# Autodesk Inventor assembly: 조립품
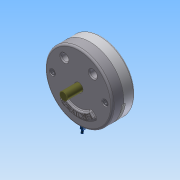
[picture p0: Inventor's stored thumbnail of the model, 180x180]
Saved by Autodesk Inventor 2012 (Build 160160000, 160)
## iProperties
Created: 2015-04
Part Number: 조립품
Document SubType Name: Assembly
Designer: net
Author: net
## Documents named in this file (10)
- C:\Users\net\Desktop\450405V1014\조립품.iam
- C:\Users\net\Desktop\450405V1014\본체.ipt
- C:\Users\net\Desktop\450405V1014\덮개.ipt
- C:\Users\net\Desktop\450405V1014\베어링62_22.ipt
- C:\Users\net\Desktop\450405V1014\축.ipt
- C:\Users\net\Desktop\450405V1014\멈춤링.ipt
- C:\Users\net\Desktop\450405V1014\슬라이더.ipt
- C:\Users\net\Desktop\450405V1014\슬라이더2.ipt
- C:\Users\net\Desktop\450405V1014\평행핀.ipt
- C:\Users\net\Desktop\450405V1014\M 10 x 35.ipt
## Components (2 placed, 1 different names)
1. M 10 x 35:1
2. M 10 x 35:2
